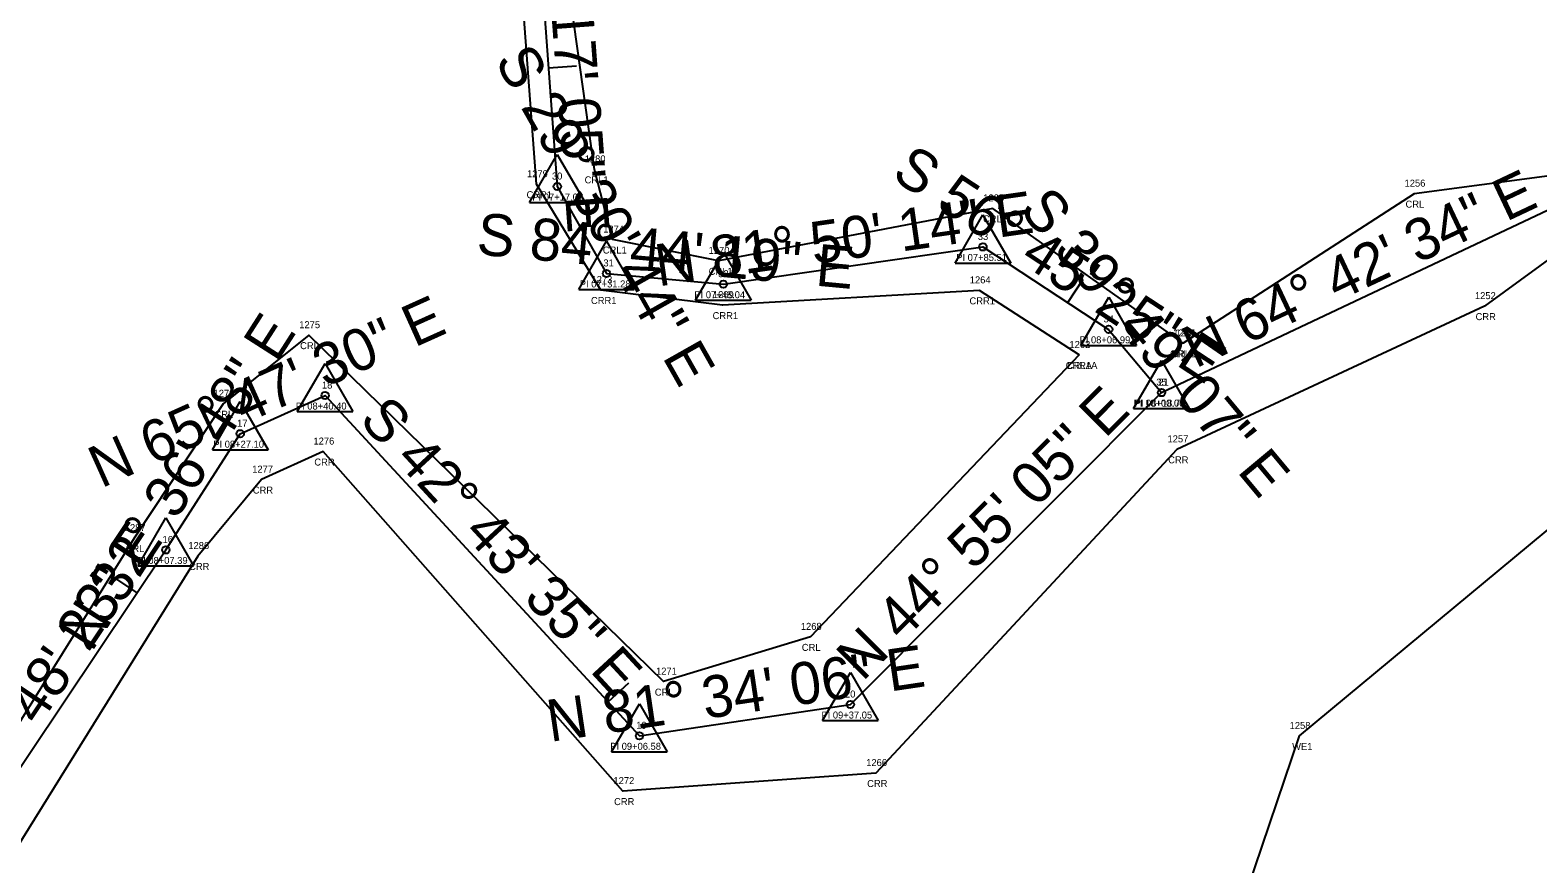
# Model space of a CAD drawing. Extents: x 2445178 to 2446205, y 790762 to 792372.
# Drawn here: x 2445380.3 to 2445595.7, y 791674.7 to 791793.8 of the extents above; entities that cross this region are included whole.
import ezdxf

# ---------------------------------------------------------------- set-up
doc = ezdxf.new("R2010")
doc.units = 0
for name, color, linetype in [('RD_EX_H2O', 7, 'Continuous'), ('RD_EX_H2O_txCode', 7, 'Continuous'), ('RD_HC_Cl', 7, 'Continuous'), ('RD_HC_Data', 7, 'Continuous'), ('RD_HC_Data_Tic', 7, 'Continuous'), ('RD_HC_txCode', 7, 'Continuous'), ('RD_SMD_Locator', 7, 'Continuous')]:
    doc.layers.add(name, color=color, linetype=linetype)

msp = doc.modelspace()

# ---------------------------------------------------------------- linework, layer by layer
at = {"layer": 'RD_EX_H2O'}
for points in [[(2445544.99, 791749.08), (2445517.8, 791768.36), (2445478.59, 791760.86), (2445463.48, 791763.9), (2445460.87, 791773.93), (2445455.89, 791809.54), (2445415.21, 791826.15)], [(2445530.12, 791747.41), (2445515.88, 791756.64), (2445479.19, 791754.53), (2445461.81, 791756.69), (2445452.6, 791771.81), (2445450.18, 791804.36), (2445403.09, 791820.76)], [(2445748.32, 791780.49), (2445701.12, 791774.43), (2445677.09, 791767.59), (2445662.39, 791761.56), (2445644.36, 791766.93), (2445623.55, 791762.71), (2445618.49, 791746.46), (2445607.67, 791748.78), (2445606.64, 791748.27), (2445612.18, 791734.98), (2445561.56, 791692.97), (2445554.1, 791670.89), (2445517.8, 791656.91), (2445473.7, 791621.85), (2445363.77, 791592.3), (2445292.26, 791558.82)], [(2445597.34, 791773), (2445578, 791770.46), (2445544.99, 791749.08)], [(2445601.06, 791763.87), (2445588.04, 791754.39), (2445544.11, 791733.92), (2445501.1, 791687.67), (2445464.95, 791685.09), (2445422.11, 791733.61), (2445413.32, 791729.6), (2445404.23, 791718.68), (2445377.21, 791675.18), (2445369.95, 791673.71), (2445335.95, 791691.26), (2445308.99, 791685.23), (2445308.22, 791596.59), (2445306.48, 791581.14), (2445293.31, 791557.11)], [(2445530.12, 791747.41), (2445491.74, 791707.13), (2445470.74, 791700.73), (2445420.06, 791750.24), (2445407.82, 791740.44), (2445395.12, 791721.24), (2445370.26, 791681.38), (2445332.86, 791701.82), (2445302.63, 791690.34), (2445292.86, 791599.86), (2445287.21, 791569.74)]]:
    msp.add_lwpolyline(points, dxfattribs=at)
at = {"layer": 'RD_HC_Cl'}
for p, q in [((2445452.95, 791806.64), (2445455.58, 791771.48)), ((2445455.58, 791771.48), (2445462.61, 791759.06)), ((2445541.89, 791742.03), (2445603.08, 791770.94)), ((2445479.3, 791757.52), (2445516.39, 791762.85)), ((2445516.39, 791762.85), (2445534.35, 791751.07)), ((2445462.61, 791759.06), (2445479.3, 791757.52)), ((2445534.35, 791751.07), (2445541.89, 791742.03)), ((2445410.28, 791736.16), (2445422.4, 791741.61)), ((2445422.4, 791741.61), (2445467.31, 791692.99)), ((2445497.45, 791697.46), (2445541.89, 791742.03)), ((2445399.65, 791719.55), (2445410.28, 791736.16)), ((2445371.27, 791677.17), (2445399.65, 791719.55)), ((2445467.31, 791692.99), (2445497.45, 791697.46))]:
    msp.add_line(p, q, dxfattribs=at)
at = {"layer": 'RD_HC_Data'}
for p, q in [((2445451.61, 791769.19), (2445455.58, 791776.07)), ((2445455.58, 791776.07), (2445459.55, 791769.19)), ((2445451.61, 791769.19), (2445459.55, 791769.19)), ((2445512.42, 791760.55), (2445516.39, 791767.43)), ((2445516.39, 791767.43), (2445520.36, 791760.55)), ((2445458.64, 791756.77), (2445462.61, 791763.65)), ((2445462.61, 791763.65), (2445466.58, 791756.77)), ((2445475.33, 791755.23), (2445479.3, 791762.11)), ((2445479.3, 791762.11), (2445483.27, 791755.23)), ((2445512.42, 791760.55), (2445520.36, 791760.55)), ((2445458.64, 791756.77), (2445466.58, 791756.77)), ((2445530.38, 791748.78), (2445534.36, 791755.66)), ((2445534.36, 791755.66), (2445538.32, 791748.78)), ((2445475.33, 791755.23), (2445483.27, 791755.23)), ((2445530.38, 791748.78), (2445538.32, 791748.78)), ((2445418.43, 791739.32), (2445422.4, 791746.2)), ((2445422.4, 791746.2), (2445426.37, 791739.32)), ((2445537.92, 791739.74), (2445541.89, 791746.62)), ((2445537.92, 791739.74), (2445541.89, 791746.62)), ((2445541.89, 791746.62), (2445545.86, 791739.74)), ((2445541.89, 791746.62), (2445545.86, 791739.74)), ((2445406.31, 791733.87), (2445410.28, 791740.75)), ((2445410.28, 791740.75), (2445414.25, 791733.87)), ((2445418.43, 791739.32), (2445426.37, 791739.32)), ((2445537.92, 791739.74), (2445545.86, 791739.74)), ((2445537.92, 791739.74), (2445545.86, 791739.74)), ((2445406.31, 791733.87), (2445414.25, 791733.87)), ((2445395.68, 791717.26), (2445399.65, 791724.14)), ((2445399.65, 791724.14), (2445403.62, 791717.26)), ((2445395.68, 791717.26), (2445403.62, 791717.26)), ((2445493.48, 791695.17), (2445497.45, 791702.05)), ((2445497.45, 791702.05), (2445501.42, 791695.17)), ((2445463.34, 791690.7), (2445467.31, 791697.58)), ((2445467.31, 791697.58), (2445471.28, 791690.7)), ((2445493.48, 791695.17), (2445501.42, 791695.17)), ((2445463.34, 791690.7), (2445471.28, 791690.7))]:
    msp.add_line(p, q, dxfattribs=at)
for centre in [(2445455.58, 791771.48), (2445516.39, 791762.85), (2445462.61, 791759.06), (2445479.3, 791757.52), (2445534.35, 791751.07), (2445541.89, 791742.03), (2445541.89, 791742.03), (2445422.4, 791741.61), (2445410.28, 791736.16), (2445399.65, 791719.55), (2445497.45, 791697.46), (2445467.31, 791692.99)]:
    msp.add_circle(centre, 0.529, dxfattribs=at)
at = {"layer": 'RD_HC_Data_Tic'}
for p, q in [((2445454.31, 791788.45), (2445458.3, 791788.74)), ((2445528.51, 791754.9), (2445530.7, 791758.25)), ((2445395.54, 791713.41), (2445392.22, 791715.64)), ((2445462.84, 791697.83), (2445465.78, 791700.54))]:
    msp.add_line(p, q, dxfattribs=at)
at = {"layer": 'RD_SMD_Locator'}
for centre in [(2445460.87, 791773.93), (2445452.6, 791771.81), (2445455.58, 791771.48), (2445578, 791770.46), (2445517.8, 791768.36), (2445463.48, 791763.9), (2445516.39, 791762.85), (2445478.59, 791760.86), (2445462.61, 791759.06), (2445461.81, 791756.69), (2445479.3, 791757.52), (2445515.88, 791756.64), (2445479.19, 791754.53), (2445588.04, 791754.39), (2445420.06, 791750.24), (2445534.35, 791751.07), (2445544.99, 791749.08), (2445544.99, 791749.08), (2445530.12, 791747.41), (2445530.12, 791747.41), (2445407.82, 791740.44), (2445422.4, 791741.61), (2445541.89, 791742.03), (2445541.89, 791742.03), (2445410.28, 791736.16), (2445422.11, 791733.61), (2445544.11, 791733.92), (2445413.32, 791729.6), (2445395.12, 791721.24), (2445399.65, 791719.55), (2445404.23, 791718.68), (2445491.74, 791707.13), (2445470.74, 791700.73), (2445497.45, 791697.46), (2445467.31, 791692.99), (2445561.56, 791692.97), (2445501.1, 791687.67), (2445464.95, 791685.09)]:
    msp.add_circle(centre, 0.001, dxfattribs=at)

# ---------------------------------------------------------------- texts
at = {"layer": 'RD_EX_H2O_txCode'}
for s, p in [('1280', (2445459.49, 791774.93)), ('1279', (2445451.25, 791772.81)), ('CRL1', (2445459.48, 791771.93)), ('CRR1', (2445451.18, 791769.81)), ('1256', (2445576.63, 791771.46)), ('1265', (2445516.43, 791769.36)), ('CRL', (2445576.77, 791768.46)), ('CRL1', (2445516.4, 791766.36)), ('1274', (2445462.13, 791764.9)), ('CRL1', (2445462.08, 791761.9)), ('1270', (2445477.2, 791761.86)), ('CRL1', (2445477.2, 791758.86)), ('1273', (2445460.46, 791757.69)), ('1264', (2445514.51, 791757.64)), ('CRR1', (2445460.39, 791754.69)), ('1269', (2445477.82, 791755.53)), ('CRR1', (2445514.47, 791754.64)), ('1252', (2445586.69, 791755.39)), ('CRR1', (2445477.77, 791752.53)), ('CRR', (2445586.78, 791752.39)), ('1275', (2445418.71, 791751.24)), ('CRL', (2445418.83, 791748.24)), ('1262', (2445528.75, 791748.41)), ('1263', (2445528.75, 791748.41)), ('1260', (2445543.58, 791750.08)), ('1261', (2445543.9, 791750.08)), ('CRL1A', (2445543.11, 791747.08)), ('CRLB', (2445543.29, 791747.08)), ('CRR1A', (2445528.21, 791745.41)), ('CRLA', (2445528.4, 791745.41)), ('1278', (2445406.47, 791741.44)), ('CRL', (2445406.59, 791738.44)), ('1276', (2445420.74, 791734.61)), ('1257', (2445542.76, 791734.92)), ('CRR', (2445420.86, 791731.61)), ('CRR', (2445542.86, 791731.92)), ('1277', (2445411.98, 791730.6)), ('CRR', (2445412.07, 791727.6)), ('1287', (2445393.78, 791722.24)), ('CRL', (2445393.9, 791719.24)), ('1286', (2445402.86, 791719.68)), ('CRR', (2445402.97, 791716.68)), ('1268', (2445490.37, 791708.13)), ('CRL', (2445490.51, 791705.13)), ('1271', (2445469.68, 791701.73)), ('CRL', (2445469.51, 791698.73)), ('1258', (2445560.21, 791693.97)), ('WE1', (2445560.57, 791690.97)), ('1266', (2445499.71, 791688.67)), ('1272', (2445463.6, 791686.09)), ('CRR', (2445499.85, 791685.67)), ('CRR', (2445463.69, 791683.09))]:
    msp.add_text(s, height=1, dxfattribs=at).set_placement(p)
at = {"layer": 'RD_HC_Data'}
for s, rotation, p in [('S 4%%d 17\' 05" E', 274.2847, (2445453.39, 791814.11)), ('S 29%%d 30\' 44" E', 299.5122, (2445446.55, 791789.47)), ('S 56%%d 45\' 25" E', 326.7569, (2445503.14, 791772.73)), ('N 64%%d 42\' 34" E', 25.2905, (2445546.76, 791745.44)), ('N 81%%d 50\' 14" E', 8.1628, (2445470.01, 791757.2)), ('S 39%%d 49\' 07" E', 309.8187, (2445521.45, 791768.12)), ('S 84%%d 44\' 19" E', 354.7385, (2445443.92, 791761.79)), ('N 65%%d 47\' 30" E', 24.2083, (2445390.41, 791728.32)), ('N 32%%d 36\' 48" E', 57.3867, (2445389.04, 791704.83)), ('N 44%%d 55\' 05" E', 45.0818, (2445499.21, 791700.64)), ('S 42%%d 43\' 35" E', 312.7263, (2445427.1, 791737.99)), ('N 33%%d 48\' 23" E', 56.1936, (2445369.06, 791675.67)), ('N 81%%d 34\' 06" E', 8.4316, (2445454.55, 791692.11))]:
    msp.add_text(s, height=6, rotation=rotation, dxfattribs=at).set_placement(p)
at = {"layer": 'RD_HC_txCode'}
for s, p in [('30', (2445454.81, 791772.48)), ('PI 07+17.01', (2445452.01, 791769.48)), ('33', (2445515.66, 791763.85)), ('31', (2445462.16, 791760.06)), ('PI 07+85.51', (2445512.57, 791760.85)), ('PI 07+31.28', (2445458.79, 791757.06)), ('32', (2445478.57, 791758.52)), ('PI 07+48.04', (2445475.16, 791755.52)), ('34', (2445533.62, 791752.07)), ('PI 08+06.99', (2445530.19, 791749.07)), ('18', (2445421.95, 791742.61)), ('35', (2445541.16, 791743.03)), ('21', (2445541.44, 791743.03)), ('PI 08+40.40', (2445418.22, 791739.61)), ('PI 10+00.00', (2445537.92, 791740.03)), ('PI 08+18.76', (2445538.05, 791740.03)), ('17', (2445409.83, 791737.16)), ('PI 08+27.10', (2445406.42, 791734.16)), ('16', (2445399.18, 791720.55)), ('PI 08+07.39', (2445395.51, 791717.55)), ('20', (2445496.68, 791698.46)), ('PI 09+37.05', (2445493.31, 791695.46)), ('19', (2445466.86, 791693.99)), ('PI 09+06.58', (2445463.14, 791690.99))]:
    msp.add_text(s, height=1, dxfattribs=at).set_placement(p)

doc.saveas('drawing.dxf')
